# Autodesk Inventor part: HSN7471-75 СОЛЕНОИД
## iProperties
Created: 2011-02
Part Number: HSN7471-75 СОЛЕНОИД
Document SubType Name: Modeling
Designer: Чернышев Юрий
Mass: 71.2732 g
Surface Area: 137.483 cm^2
Volume: 71.2732 cm^3
Density: 1 g/cm^3
Author: Чернышев Юрий
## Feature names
1. ExtrusionBlind1
2. ExtrusionBlind2
3. Fillet1
4. ExtrusionBlind3
5. ExtrusionBlind4
6. RevolutionAngle1
7. ExtrusionBlind5
8. Hole1
9. Hole2
